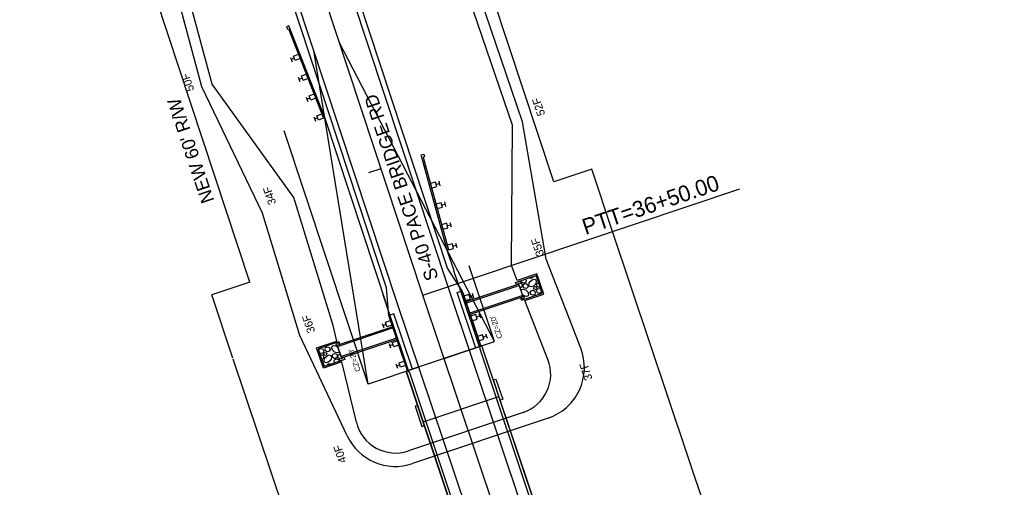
# Model space of a CAD drawing. Extents: x 1528853 to 1624411, y 1119753 to 1162242.
# Drawn here: x 1529349 to 1529722.2, y 1160646.4 to 1160821.6 of the extents above; entities that cross this region are included whole.
import ezdxf

# ---------------------------------------------------------------- set-up
doc = ezdxf.new("R2010")
doc.units = 0
for name, color, linetype in [('BR_CONCRETE', 7, 'Continuous'), ('Drainage-Trench', 7, 'Continuous'), ('RD_EX_Road Text', 7, 'Continuous'), ('RD_HC_Cl', 7, 'Continuous'), ('RD_HC_Data', 7, 'Continuous'), ('RD_HC_Data_Tic', 7, 'Continuous'), ('RD_PD_BOC', 7, 'Continuous'), ('RD_PD_CstnLmt', 7, 'Continuous'), ('RD_PD_CstnLmt_TX', 7, 'Continuous'), ('RD_PD_DR_ErosCtrl', 7, 'Continuous'), ('RD_PD_DR_Inlet', 7, 'Continuous'), ('RD_PD_Final_TrvlWay', 7, 'Continuous'), ('RD_PD_GR', 7, 'Continuous'), ('RD_PD_PaveDit', 7, 'Continuous'), ('RD_PD_PaveShd', 7, 'Continuous'), ('RD_PD_RW', 7, 'Continuous'), ('RD_Sketch8', 7, 'Continuous')]:
    doc.layers.add(name, color=color, linetype=linetype)

# ---------------------------------------------------------------- blocks, each defined once
blk = doc.blocks.new('Guardrail_MTBBC2_Transition')
at = {"layer": 'RD_PD_GR'}
for p, q in [((3.875, 3.75), (2.125, 3.75)), ((3, 2.5), (3, 3.75)), ((11.875, 3.75), (10.125, 3.75)), ((11, 2.5), (11, 3.75)), ((19.875, 3.75), (18.125, 3.75)), ((19, 2.5), (19, 3.75)), ((0, 0.5), (0, 0)), ((21.25, 0.5), (0, 0.5)), ((0, 0), (21.25, 0)), ((2.125, 0.5), (2.125, 2.5)), ((2.125, 2.5), (3.875, 2.5)), ((3.875, 0.5), (2.125, 0.5)), ((3.875, 2.5), (3.875, 0.5)), ((10.125, 0.5), (10.125, 2.5)), ((10.125, 2.5), (11.875, 2.5)), ((11.875, 0.5), (10.125, 0.5)), ((11.875, 2.5), (11.875, 0.5)), ((15, 0.5), (15, 0)), ((18.125, 0.5), (18.125, 2.5)), ((18.125, 2.5), (19.875, 2.5)), ((19.875, 0.5), (18.125, 0.5)), ((19.875, 2.5), (19.875, 0.5)), ((21.25, 0), (21.25, 0.5))]:
    blk.add_line(p, q, dxfattribs=at)

msp = doc.modelspace()

# ---------------------------------------------------------------- linework, layer by layer
at = {"layer": 'BR_CONCRETE'}
for p, q in [((1529522.3, 1160699.42), (1529493.86, 1160689.87)), ((1529521.59, 1160698.13), (1529521.51, 1160699.15)), ((1529559.16, 1160586.27), (1529521.59, 1160698.13)), ((1529560.43, 1160585.64), (1529522.22, 1160699.39)), ((1529560.51, 1160585.66), (1529522.3, 1160699.42)), ((1529532.07, 1160576.11), (1529493.86, 1160689.87)), ((1529532.15, 1160576.14), (1529493.94, 1160689.89)), ((1529495.2, 1160689.26), (1529494.65, 1160690.13)), ((1529532.78, 1160577.4), (1529495.2, 1160689.26)), ((1529500.23, 1160670.91), (1529528.66, 1160680.46))]:
    msp.add_line(p, q, dxfattribs=at)
for points in [[(1529530.09, 1160679.36), (1529529.14, 1160679.04), (1529526.6, 1160686.62), (1529527.54, 1160686.94)], [(1529499.76, 1160669.17), (1529500.7, 1160669.48), (1529498.16, 1160677.07), (1529497.21, 1160676.75)]]:
    msp.add_lwpolyline(points, close=True, dxfattribs=at)
at = {"layer": 'Drainage-Trench'}
for p, q in [((1529534.9, 1160723.17), (1529542.59, 1160725.75)), ((1529544.82, 1160719.12), (1529542.59, 1160725.75)), ((1529535.22, 1160722.22), (1529534.9, 1160723.17)), ((1529537.76, 1160717.8), (1529536.16, 1160722.54)), ((1529537.13, 1160716.53), (1529536.81, 1160717.48)), ((1529537.13, 1160716.53), (1529544.82, 1160719.12)), ((1529468.64, 1160700.91), (1529460.94, 1160698.32)), ((1529460.94, 1160698.32), (1529463.17, 1160691.69)), ((1529468.01, 1160699.64), (1529469.6, 1160694.9)), ((1529468.64, 1160700.91), (1529468.96, 1160699.96)), ((1529470.87, 1160694.27), (1529463.17, 1160691.69)), ((1529470.55, 1160695.22), (1529470.87, 1160694.27))]:
    msp.add_line(p, q, dxfattribs=at)
at = {"layer": 'RD_HC_Cl'}
for p, q in [((1529500.12, 1160718.34), (1529406.02, 1161003.2)), ((1529913.5, 1159487.74), (1529500.12, 1160718.34))]:
    msp.add_line(p, q, dxfattribs=at)
at = {"layer": 'RD_HC_Data'}
msp.add_line((1529500.12, 1160718.34), (1529619.02, 1160758.28), dxfattribs=at)
at = {"layer": 'RD_HC_Data_Tic'}
msp.add_line((1529484.43, 1160765.82), (1529479.69, 1160764.25), dxfattribs=at)
at = {"layer": 'RD_PD_BOC'}
for p, q in [((1529512.96, 1160719.36), (1529514.86, 1160719.99)), ((1529519.94, 1160698.58), (1529512.96, 1160719.35)), ((1529521.84, 1160699.22), (1529514.86, 1160719.99)), ((1529489.25, 1160711.44), (1529487.35, 1160710.8)), ((1529494.33, 1160690.03), (1529487.35, 1160710.8)), ((1529496.23, 1160690.66), (1529489.25, 1160711.44))]:
    msp.add_line(p, q, dxfattribs=at)
at = {"layer": 'RD_PD_CstnLmt'}
for p, q in [((1529421.11, 1160797.56), (1529408.14, 1160845.93)), ((1529533.7, 1160782.09), (1529517.58, 1160829.42)), ((1529451.8, 1160755.04), (1529421.11, 1160797.56)), ((1529533.33, 1160729.5), (1529533.7, 1160782.09)), ((1529466.45, 1160707.03), (1529451.8, 1160755.04)), ((1529535.51, 1160723.9), (1529533.33, 1160729.5)), ((1529542.91, 1160726.39), (1529535.51, 1160723.9)), ((1529545.46, 1160718.8), (1529542.91, 1160726.39)), ((1529538.41, 1160716.44), (1529545.46, 1160718.8)), ((1529547.05, 1160694.24), (1529538.41, 1160716.44)), ((1529467.86, 1160701.18), (1529466.45, 1160707.03)), ((1529460.31, 1160698.64), (1529467.86, 1160701.18)), ((1529462.85, 1160691.06), (1529460.31, 1160698.64)), ((1529469.75, 1160693.37), (1529462.85, 1160691.06)), ((1529475.22, 1160670.74), (1529469.75, 1160693.37)), ((1529537.79, 1160674.46), (1529494.69, 1160659.98))]:
    msp.add_line(p, q, dxfattribs=at)
for centre, start, end in [((1529532.98, 1160688.77), 288.568, 21.2575), ((1529489.89, 1160674.29), 193.5876, 288.568)]:
    msp.add_arc(centre, 15.09, start, end, dxfattribs=at)
at = {"layer": 'RD_PD_DR_ErosCtrl'}
for p, q in [((1529417.25, 1160796.52), (1529404.28, 1160844.86)), ((1529537.49, 1160783.38), (1529521.32, 1160830.85)), ((1529440, 1160749.18), (1529417.25, 1160796.52)), ((1529546.35, 1160731.89), (1529537.49, 1160783.38)), ((1529454.01, 1160703.24), (1529440, 1160749.18)), ((1529559.34, 1160698.51), (1529546.35, 1160731.89)), ((1529471.71, 1160665.72), (1529454.01, 1160703.24)), ((1529547.06, 1160672.3), (1529496.29, 1160655.24))]:
    msp.add_line(p, q, dxfattribs=at)
for centre, radius, start, end in [((1529540.7, 1160691.26), 20, 288.568, 21.2575), ((1529489.89, 1160674.29), 20.09, 205.2589, 288.568)]:
    msp.add_arc(centre, radius, start, end, dxfattribs=at)
at = {"layer": 'RD_PD_DR_Inlet'}
for p, q in [((1529536.16, 1160722.54), (1529515.91, 1160715.73)), ((1529536.32, 1160722.06), (1529516.07, 1160715.26)), ((1529537.76, 1160717.8), (1529536.16, 1160722.54)), ((1529537.6, 1160718.27), (1529517.34, 1160711.47)), ((1529537.76, 1160717.8), (1529517.5, 1160710.99)), ((1529468.01, 1160699.64), (1529489.38, 1160706.82)), ((1529468.17, 1160699.17), (1529489.54, 1160706.35)), ((1529469.44, 1160695.38), (1529490.81, 1160702.56)), ((1529469.6, 1160694.9), (1529490.97, 1160702.08)), ((1529469.6, 1160694.9), (1529468.01, 1160699.64))]:
    msp.add_line(p, q, dxfattribs=at)
at = {"layer": 'RD_PD_Final_TrvlWay'}
for p, q in [((1529509.61, 1160721.48), (1529415.51, 1161006.34)), ((1529490.62, 1160715.2), (1529396.52, 1161000.06)), ((1529628.69, 1160366.99), (1529509.6, 1160721.52)), ((1529609.73, 1160360.62), (1529490.64, 1160715.16))]:
    msp.add_line(p, q, dxfattribs=at)
at = {"layer": 'RD_PD_GR'}
for p, q in [((1529449.88, 1160819.41), (1529448.95, 1160819.04)), ((1529448.95, 1160819.04), (1529449.32, 1160818.11)), ((1529449.32, 1160818.11), (1529449.78, 1160818.29)), ((1529449.78, 1160818.29), (1529462.9, 1160784.77)), ((1529463.37, 1160784.95), (1529449.88, 1160819.41)), ((1529451.06, 1160815.03), (1529451.52, 1160815.21)), ((1529450.49, 1160807.56), (1529451.13, 1160805.93)), ((1529451.97, 1160807.2), (1529450.81, 1160806.75)), ((1529451.66, 1160808.02), (1529453.52, 1160808.75)), ((1529452.29, 1160806.39), (1529451.66, 1160808.02)), ((1529454.16, 1160807.12), (1529452.29, 1160806.39)), ((1529453.52, 1160808.75), (1529454.16, 1160807.12)), ((1529453.41, 1160800.11), (1529454.04, 1160798.48)), ((1529454.89, 1160799.75), (1529453.73, 1160799.3)), ((1529454.57, 1160800.57), (1529456.43, 1160801.3)), ((1529455.21, 1160798.94), (1529454.57, 1160800.57)), ((1529457.07, 1160799.67), (1529455.21, 1160798.94)), ((1529456.43, 1160801.3), (1529457.07, 1160799.67)), ((1529456.32, 1160792.66), (1529456.96, 1160791.03)), ((1529457.81, 1160792.3), (1529456.64, 1160791.85)), ((1529457.49, 1160793.12), (1529459.35, 1160793.85)), ((1529458.12, 1160791.49), (1529457.49, 1160793.12)), ((1529459.99, 1160792.22), (1529458.12, 1160791.49)), ((1529459.35, 1160793.85), (1529459.99, 1160792.22)), ((1529459.24, 1160785.21), (1529459.88, 1160783.58)), ((1529460.72, 1160784.85), (1529459.56, 1160784.4)), ((1529460.4, 1160785.67), (1529462.27, 1160786.4)), ((1529461.04, 1160784.04), (1529460.4, 1160785.67)), ((1529462.9, 1160784.77), (1529461.04, 1160784.04)), ((1529462.27, 1160786.4), (1529462.9, 1160784.77)), ((1529462.9, 1160784.77), (1529463.37, 1160784.95)), ((1529486.85, 1160713.88), (1529463.37, 1160784.95)), ((1529499.51, 1160770.98), (1529500.47, 1160771.24)), ((1529509.24, 1160735.28), (1529499.51, 1160770.98)), ((1529500.73, 1160770.27), (1529500.25, 1160770.14)), ((1529500.25, 1160770.14), (1529509.72, 1160735.41)), ((1529500.47, 1160771.24), (1529500.73, 1160770.27)), ((1529501.17, 1160766.77), (1529500.69, 1160766.63)), ((1529504.88, 1160760.78), (1529502.95, 1160760.25)), ((1529502.95, 1160760.25), (1529503.41, 1160758.57)), ((1529503.41, 1160758.57), (1529505.34, 1160759.09)), ((1529505.34, 1160759.09), (1529504.88, 1160760.78)), ((1529505.11, 1160759.94), (1529506.31, 1160760.26)), ((1529506.08, 1160761.11), (1529506.54, 1160759.42)), ((1529506.98, 1160753.06), (1529505.05, 1160752.54)), ((1529505.05, 1160752.54), (1529505.51, 1160750.85)), ((1529505.51, 1160750.85), (1529507.44, 1160751.37)), ((1529507.44, 1160751.37), (1529506.98, 1160753.06)), ((1529507.21, 1160752.22), (1529508.42, 1160752.55)), ((1529508.19, 1160753.39), (1529508.65, 1160751.7)), ((1529509.09, 1160745.34), (1529507.16, 1160744.82)), ((1529507.16, 1160744.82), (1529507.62, 1160743.13)), ((1529507.62, 1160743.13), (1529509.55, 1160743.66)), ((1529509.55, 1160743.66), (1529509.09, 1160745.34)), ((1529509.32, 1160744.5), (1529510.52, 1160744.83)), ((1529510.29, 1160745.67), (1529510.75, 1160743.98)), ((1529509.72, 1160735.41), (1529509.24, 1160735.28)), ((1529511.82, 1160727.47), (1529509.24, 1160735.28)), ((1529511.19, 1160737.63), (1529509.26, 1160737.1)), ((1529509.26, 1160737.1), (1529509.72, 1160735.41)), ((1529509.72, 1160735.41), (1529511.65, 1160735.94)), ((1529511.65, 1160735.94), (1529511.19, 1160737.63)), ((1529511.42, 1160736.78), (1529512.63, 1160737.11)), ((1529512.4, 1160737.95), (1529512.86, 1160736.27)), ((1529514.6, 1160719.2), (1529511.8, 1160727.54)), ((1529488.04, 1160710.33), (1529485.27, 1160718.58))]:
    msp.add_line(p, q, dxfattribs=at)
at = {"layer": 'RD_PD_PaveDit'}
for p, q in [((1529540.71, 1160724.63), (1529539.94, 1160724.86)), ((1529536.82, 1160723.45), (1529536.58, 1160723.73)), ((1529536.69, 1160721.16), (1529536.62, 1160721.18)), ((1529537.73, 1160718.35), (1529537.47, 1160718.66)), ((1529468.04, 1160699.09), (1529468.3, 1160698.78)), ((1529469.08, 1160696.28), (1529469.14, 1160696.27)), ((1529465.06, 1160692.81), (1529465.82, 1160692.58)), ((1529468.95, 1160693.99), (1529469.18, 1160693.71))]:
    msp.add_line(p, q, dxfattribs=at)
for points in [[(1529538.68, 1160724.44), (1529538.9, 1160723.84), (1529538.71, 1160723.24), (1529538.04, 1160722.96), (1529537.29, 1160723.15), (1529536.78, 1160723.48)], [(1529540.32, 1160723.55), (1529541.09, 1160724.2), (1529541.94, 1160724.41), (1529542.45, 1160724.17), (1529542.67, 1160723.5), (1529542.33, 1160722.54), (1529541.57, 1160721.78), (1529540.71, 1160721.47), (1529540.11, 1160721.65), (1529539.83, 1160722.32), (1529540.02, 1160723.07), (1529540.35, 1160723.58)], [(1529541.46, 1160725.37), (1529541.26, 1160724.95), (1529540.71, 1160724.63)], [(1529542.79, 1160725.18), (1529542.58, 1160725.42), (1529542.51, 1160725.72)], [(1529535.66, 1160722.37), (1529535.92, 1160722.87), (1529536.72, 1160723.05), (1529537.27, 1160722.71), (1529537.46, 1160721.94), (1529537.24, 1160721.47), (1529536.69, 1160721.16)], [(1529536.96, 1160720.17), (1529537.11, 1160720.49), (1529537.78, 1160720.7), (1529538.73, 1160720.36), (1529539.5, 1160719.6), (1529539.8, 1160718.74), (1529539.62, 1160718.14), (1529538.95, 1160717.86), (1529538.2, 1160718.05), (1529537.69, 1160718.38)], [(1529538.79, 1160720.86), (1529537.95, 1160721.11), (1529537.65, 1160721.86), (1529538.02, 1160722.57), (1529538.82, 1160722.76), (1529539.37, 1160722.42), (1529539.57, 1160721.65), (1529539.34, 1160721.18), (1529538.79, 1160720.86)], [(1529542.37, 1160720.48), (1529541.86, 1160720.63), (1529541.68, 1160721.08), (1529541.9, 1160721.51), (1529542.38, 1160721.62), (1529542.71, 1160721.41), (1529542.83, 1160720.95), (1529542.7, 1160720.67), (1529542.37, 1160720.48)], [(1529543.93, 1160721.28), (1529543.09, 1160721.52), (1529542.79, 1160722.27), (1529543.16, 1160722.99), (1529543.5, 1160723.07)], [(1529543.93, 1160719.03), (1529543.09, 1160719.28), (1529542.79, 1160720.03), (1529543.16, 1160720.74), (1529543.96, 1160720.92), (1529544.28, 1160720.72)], [(1529544.07, 1160721.36), (1529543.93, 1160721.28)], [(1529537.62, 1160716.94), (1529537.11, 1160717.09), (1529536.94, 1160717.52)], [(1529537.67, 1160718.06), (1529537.97, 1160717.87), (1529538.09, 1160717.41), (1529537.95, 1160717.13), (1529537.62, 1160716.94)], [(1529541.52, 1160718.37), (1529540.68, 1160718.62), (1529540.38, 1160719.37), (1529540.76, 1160720.08), (1529541.55, 1160720.26), (1529542.1, 1160719.93), (1529542.3, 1160719.15), (1529542.08, 1160718.68), (1529541.52, 1160718.37)], [(1529544.64, 1160719.67), (1529544.48, 1160719.34), (1529543.93, 1160719.03)], [(1529461.13, 1160697.77), (1529461.28, 1160698.1), (1529461.83, 1160698.41)], [(1529461.83, 1160698.41), (1529462.67, 1160698.16), (1529462.97, 1160697.41), (1529462.6, 1160696.7), (1529461.81, 1160696.52), (1529461.48, 1160696.72)], [(1529464.24, 1160699.07), (1529465.08, 1160698.82), (1529465.38, 1160698.07), (1529465.01, 1160697.36), (1529464.21, 1160697.18), (1529463.66, 1160697.52), (1529463.46, 1160698.29), (1529463.69, 1160698.76), (1529464.24, 1160699.07)], [(1529468.81, 1160697.27), (1529468.66, 1160696.95), (1529467.99, 1160696.74), (1529467.03, 1160697.08), (1529466.27, 1160697.84), (1529465.96, 1160698.7), (1529466.14, 1160699.3), (1529466.81, 1160699.58), (1529467.56, 1160699.39), (1529468.07, 1160699.06)], [(1529468.09, 1160699.39), (1529467.8, 1160699.57), (1529467.68, 1160700.03), (1529467.81, 1160700.31), (1529468.15, 1160700.5)], [(1529468.15, 1160700.5), (1529468.65, 1160700.35), (1529468.82, 1160699.92)], [(1529461.69, 1160696.08), (1529461.84, 1160696.17)], [(1529461.84, 1160696.17), (1529462.68, 1160695.92), (1529462.98, 1160695.17), (1529462.61, 1160694.45), (1529462.27, 1160694.38)], [(1529463.4, 1160696.96), (1529463.9, 1160696.81), (1529464.08, 1160696.36), (1529463.86, 1160695.93), (1529463.38, 1160695.82), (1529463.05, 1160696.03), (1529462.93, 1160696.49), (1529463.07, 1160696.77), (1529463.4, 1160696.96)], [(1529465.45, 1160693.89), (1529464.67, 1160693.24), (1529463.82, 1160693.03), (1529463.31, 1160693.27), (1529463.1, 1160693.94), (1529463.44, 1160694.9), (1529464.2, 1160695.67), (1529465.06, 1160695.97), (1529465.66, 1160695.79), (1529465.93, 1160695.12), (1529465.75, 1160694.37), (1529465.42, 1160693.86)], [(1529466.98, 1160696.58), (1529467.82, 1160696.33), (1529468.12, 1160695.58), (1529467.74, 1160694.87), (1529466.95, 1160694.68), (1529466.4, 1160695.02), (1529466.2, 1160695.8), (1529466.42, 1160696.27), (1529466.98, 1160696.58)], [(1529467.08, 1160693), (1529466.87, 1160693.6), (1529467.05, 1160694.2), (1529467.72, 1160694.48), (1529468.47, 1160694.29), (1529468.98, 1160693.96)], [(1529470.11, 1160695.07), (1529469.84, 1160694.57), (1529469.05, 1160694.39), (1529468.5, 1160694.73), (1529468.3, 1160695.5), (1529468.52, 1160695.97), (1529469.08, 1160696.28)], [(1529462.98, 1160692.26), (1529463.18, 1160692.02), (1529463.25, 1160691.72)], [(1529464.3, 1160692.07), (1529464.5, 1160692.49), (1529465.06, 1160692.81)]]:
    msp.add_lwpolyline(points, dxfattribs=at)
at = {"layer": 'RD_PD_PaveShd'}
for p, q in [((1529509.38, 1160728.57), (1529417.41, 1161006.96)), ((1529486.53, 1160721.21), (1529394.62, 1160999.44)), ((1529514.86, 1160719.99), (1529509.38, 1160728.57)), ((1529487.35, 1160710.8), (1529486.53, 1160721.21))]:
    msp.add_line(p, q, dxfattribs=at)
at = {"layer": 'RD_PD_RW'}
for p, q in [((1529549.25, 1160760.9), (1529462.99, 1161022.02)), ((1529435.3, 1160723.26), (1529349.04, 1160984.38)), ((1529563.49, 1160765.6), (1529549.25, 1160760.9)), ((1529571.33, 1160741.87), (1529563.49, 1160765.6)), ((1529881.68, 1159817.98), (1529571.21, 1160742.22)), ((1529435.3, 1160723.26), (1529421.06, 1160718.55)), ((1529428.9, 1160694.82), (1529421.06, 1160718.55)), ((1529715.61, 1159841.31), (1529429.02, 1160694.46))]:
    msp.add_line(p, q, dxfattribs=at)
at = {"layer": 'RD_Sketch8'}
for p, q in [((1529479.64, 1160685.09), (1529459.27, 1160810.11)), ((1529527.04, 1160701.01), (1529468.75, 1160813.3)), ((1529479.64, 1160685.09), (1529448.16, 1160780.01)), ((1529479.64, 1160685.09), (1529448.16, 1160780.01)), ((1529527.04, 1160701.01), (1529517.48, 1160729.45)), ((1529508.08, 1160694.64), (1529527.04, 1160701.01)), ((1529498.6, 1160691.46), (1529479.64, 1160685.09))]:
    msp.add_line(p, q, dxfattribs=at)

# ---------------------------------------------------------------- block references
at = {"layer": 'RD_PD_BOC', "yscale": -0.9999999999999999, "rotation": 108.56800570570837}
msp.add_blockref('Guardrail_MTBBC2_Transition', (1529521.36, 1160699.06), dxfattribs=at)
at = {"layer": 'RD_PD_BOC', "rotation": 108.5680057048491}
msp.add_blockref('Guardrail_MTBBC2_Transition', (1529494.81, 1160690.19), dxfattribs=at)

# ---------------------------------------------------------------- texts
at = {"layer": 'RD_EX_Road Text'}
msp.add_text('S-40 PACE BRIDGE RD', height=5, rotation=108.5527, dxfattribs=at).set_placement((1529506.06, 1160724.86))
at = {"layer": 'RD_HC_Data'}
msp.add_text('PTT=36+50.00', height=6, rotation=18.568, dxfattribs=at).set_placement((1529561.1, 1160740.93))
at = {"layer": 'RD_PD_CstnLmt_TX'}
for s, rotation, p in [('50F', 108.2806, (1529414.46, 1160795.36)), ('52F', 108.2806, (1529546.04, 1160786.17)), ('34F', 108.2806, (1529445.16, 1160752.84)), ('35F', 108.568, (1529545.65, 1160733.64)), ('36F', 108.568, (1529459.81, 1160704.8)), ('37F', 108.568, (1529563.8, 1160686.99)), ('40F', 108.568, (1529471.6, 1160656.02))]:
    msp.add_text(s, height=3, rotation=rotation, dxfattribs=at).set_placement(p)
at = {"layer": 'RD_PD_RW'}
msp.add_text("NEW 60' R/W", height=5, rotation=108.5527, dxfattribs=at).set_placement((1529422.02, 1160753.87))
at = {"layer": 'RD_Sketch8'}
for p in [(1529529.98, 1160702.47), (1529476.84, 1160690.08)]:
    msp.add_text("CZ=20'", height=2, rotation=108.3453, dxfattribs=at).set_placement(p)

doc.saveas('drawing.dxf')
